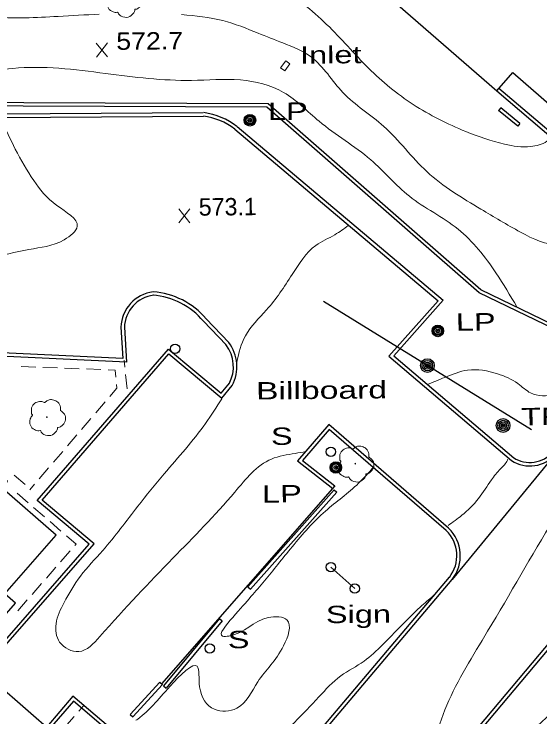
# Model space of a CAD drawing. Extents: x 2361708 to 2370558, y 6977955 to 6991887.
# Drawn here: x 2368753.8 to 2368899.2, y 6990434.2 to 6990628.6 of the extents above; entities that cross this region are included whole.
import ezdxf

# ---------------------------------------------------------------- set-up
doc = ezdxf.new("R2010")
doc.units = 0
doc.header["$LTSCALE"] = 1.9
for name, color, linetype, lineweight in [('11', 7, 'Continuous', 25), ('13', 7, 'Continuous', 13), ('2', 7, 'Continuous', 25), ('20', 7, 'Continuous', 25), ('21', 7, 'Continuous', 25), ('23', 7, 'Continuous', 25), ('29', 7, 'Continuous', 13), ('31', 7, 'Continuous', 13), ('35', 7, 'Continuous', 13), ('9', 7, 'Continuous', 13)]:
    doc.layers.add(name, color=color, linetype=linetype, lineweight=lineweight)

msp = doc.modelspace()

# ---------------------------------------------------------------- linework, layer by layer
at = {"layer": '11'}
for points in [[(2368803.061, 6990680.605), (2368887.263, 6990607.323), (2368891.675, 6990612.405), (2368910.239, 6990596.271), (2368917.905, 6990605.094), (2368925.478, 6990598.516), (2368956.5, 6990634.183), (2368949.038, 6990640.673), (2368978.25, 6990674.242), (2368958.133, 6990691.742), (2368936.419, 6990666.784), (2368928.906, 6990673.312), (2368921.191, 6990664.449), (2368845.954, 6990729.906)], [(2368706.996, 6990535.603), (2368638.297, 6990456.356), (2368654.119, 6990442.636), (2368653.159, 6990441.537), (2368680.829, 6990417.559), (2368681.571, 6990418.406), (2368686.875, 6990413.786), (2368665.874, 6990389.665), (2368677.46, 6990379.585), (2368712.974, 6990420.375), (2368713.831, 6990419.623), (2368727.186, 6990434.921), (2368751.368, 6990413.81), (2368764.99, 6990429.41), (2368740.919, 6990450.423), (2368754.205, 6990465.65), (2368751.28, 6990468.202), (2368765.486, 6990484.458), (2368750.47, 6990497.575), (2368751.984, 6990499.31), (2368724.121, 6990523.666), (2368722.627, 6990521.962)]]:
    msp.add_lwpolyline(points, close=True, dxfattribs=at)
at = {"layer": '13'}
for p, q in [((2368784.236, 6990532.859), (2368784.445, 6990530.871)), ((2368759.814, 6990530.926), (2368755.812, 6990531.078)), ((2368765.816, 6990530.703), (2368761.815, 6990530.855)), ((2368771.818, 6990530.48), (2368767.817, 6990530.632)), ((2368777.821, 6990530.257), (2368773.819, 6990530.41)), ((2368784.654, 6990528.882), (2368785.062, 6990524.906)), ((2368785.271, 6990522.918), (2368785.271, 6990522.898)), ((2368776.405, 6990518.264), (2368779.006, 6990521.298)), ((2368772.498, 6990513.706), (2368775.099, 6990516.741)), ((2368768.602, 6990509.149), (2368771.203, 6990512.184)), ((2368764.695, 6990504.591), (2368767.296, 6990507.626)), ((2368760.788, 6990500.034), (2368763.389, 6990503.069)), ((2368753.868, 6990501.048), (2368756.883, 6990498.427)), ((2368758.176, 6990496.989), (2368759.482, 6990498.511)), ((2368754.706, 6990496.016), (2368757.731, 6990493.404)), ((2368759.243, 6990492.099), (2368762.268, 6990489.488)), ((2368763.78, 6990488.182), (2368766.806, 6990485.571)), ((2368769.348, 6990480.095), (2368766.716, 6990477.079)), ((2368765.401, 6990475.576), (2368762.77, 6990472.562)), ((2368761.454, 6990471.059), (2368758.822, 6990468.044)), ((2368757.506, 6990466.541), (2368754.875, 6990463.536)), ((2368773.046, 6990437.278), (2368771.74, 6990435.765)), ((2368770.434, 6990434.253), (2368767.823, 6990431.228))]:
    msp.add_line(p, q, dxfattribs=at)
for points in [[(2368781.962, 6990528.097), (2368781.792, 6990530.116), (2368779.821, 6990530.186)], [(2368780.302, 6990522.821), (2368782.22, 6990525.059), (2368782.13, 6990526.108)], [(2368768.318, 6990484.265), (2368770.98, 6990481.96), (2368770.664, 6990481.597)]]:
    msp.add_lwpolyline(points, dxfattribs=at)
at = {"layer": '2'}
for p, q in [((2368888.388, 6990602.604), (2368887.785, 6990601.858)), ((2368893.699, 6990598.294), (2368888.388, 6990602.604)), ((2368893.096, 6990597.548), (2368887.785, 6990601.858)), ((2368893.699, 6990598.294), (2368893.096, 6990597.548)), ((2368813.182, 6990537.734), (2368806.909, 6990544.265)), ((2368812.488, 6990537.068), (2368806.215, 6990543.599)), ((2368903.549, 6990506.893), (2368874.918, 6990472.179)), ((2368842.52, 6990498.072), (2368794.599, 6990443.323)), ((2368842.371, 6990497.01), (2368818.475, 6990470.171)), ((2368843.087, 6990496.367), (2368819.191, 6990469.528)), ((2368842.371, 6990497.01), (2368843.087, 6990496.367)), ((2368818.475, 6990470.171), (2368819.191, 6990469.528)), ((2368810.668, 6990461.357), (2368795.125, 6990442.738)), ((2368811.404, 6990460.744), (2368795.86, 6990442.125)), ((2368810.668, 6990461.357), (2368811.404, 6990460.744)), ((2368794.125, 6990443.768), (2368785.949, 6990434.83)), ((2368794.831, 6990443.125), (2368786.656, 6990434.187)), ((2368794.125, 6990443.768), (2368794.831, 6990443.125)), ((2368795.125, 6990442.738), (2368795.86, 6990442.125)), ((2368785.949, 6990434.83), (2368786.656, 6990434.187))]:
    msp.add_line(p, q, dxfattribs=at)
for points in [[(2368887.886, 6990608.059), (2368913.746, 6990586.094), (2368909.564, 6990581.064)], [(2368887.263, 6990607.323), (2368912.397, 6990585.981), (2368903.222, 6990574.913)], [(2368913.951, 6990537.274), (2368882.916, 6990552.269), (2368824.074, 6990603.741), (2368711.364, 6990604.229), (2368623.522, 6990603.912)], [(2368913.529, 6990536.41), (2368882.384, 6990551.464), (2368823.713, 6990602.788), (2368711.363, 6990603.268), (2368623.522, 6990602.952)], [(2368623.568, 6990600.173), (2368707.447, 6990600.681), (2368806.156, 6990601.31)], [(2368623.577, 6990599.213), (2368707.456, 6990599.721), (2368806.165, 6990600.35)], [(2368814.87, 6990596.733), (2368871.064, 6990549.296), (2368857.45, 6990533.946), (2368891.356, 6990505.097)], [(2368815.493, 6990597.469), (2368872.433, 6990549.399), (2368858.819, 6990534.039), (2368891.979, 6990505.833)], [(2368996.914, 6990567.865), (2368920.861, 6990477.417), (2368836.413, 6990376.958), (2368777.799, 6990307.707)], [(2368997.649, 6990567.252), (2368921.597, 6990476.803), (2368837.149, 6990376.334), (2368778.535, 6990307.084)], [(2368783.38, 6990541.931), (2368783.902, 6990533.326), (2368709.045, 6990536.823), (2368624.356, 6990539.467), (2368627.356, 6990437.531), (2368654.02, 6990440.485)], [(2368784.339, 6990541.99), (2368784.922, 6990532.315), (2368709.004, 6990535.863), (2368625.345, 6990538.476), (2368628.286, 6990438.6), (2368653.91, 6990441.444)], [(2368744.289, 6990447.324), (2368774.57, 6990481.964), (2368760.265, 6990494.049), (2368796.498, 6990535.915), (2368811.125, 6990523.714), (2368813.409, 6990526.476)], [(2368745.025, 6990446.701), (2368775.94, 6990482.067), (2368761.624, 6990494.151), (2368796.61, 6990534.577), (2368811.248, 6990522.355), (2368814.145, 6990525.863)], [(2368873.953, 6990486.41), (2368840.879, 6990515.047), (2368832.164, 6990504.973), (2368841.928, 6990497.316)], [(2368873.32, 6990485.685), (2368840.972, 6990513.687), (2368833.553, 6990505.107), (2368842.52, 6990498.072)], [(2368717.185, 6990288.919), (2368794.17, 6990378.056), (2368874.182, 6990472.802)], [(2368717.911, 6990288.296), (2368794.897, 6990377.433), (2368874.918, 6990472.179)], [(2368782.391, 6990429.386), (2368770.131, 6990439.92), (2368762.861, 6990431.45)], [(2368781.768, 6990428.66), (2368770.234, 6990438.561), (2368763.607, 6990430.837)]]:
    msp.add_lwpolyline(points, dxfattribs=at)
for centre, radius, start, end in [((2368803.828, 6990582.444), 18.058, 52.30519, 82.564), ((2368803.828, 6990582.444), 19.018, 52.30519, 82.564), ((2368793.54, 6990541.657), 10.163, 96.90872, 178.45638), ((2368790.794, 6990530.805), 20.997, 39.87055, 85.84105), ((2368793.54, 6990541.657), 9.203, 96.90872, 178.45638), ((2368790.794, 6990530.805), 20.037, 39.87055, 85.84105), ((2368804.367, 6990531.044), 10.106, 332.08022, 37.19742), ((2368804.367, 6990531.044), 11.066, 332.08022, 37.19742), ((2368896.438, 6990512.877), 9.293, 236.84602, 319.91801), ((2368896.438, 6990512.877), 8.333, 236.84602, 319.91801), ((2318071.367, 7041248.644), 71901.899, 314.92877, 315.1113), ((2368866.59, 6990478.762), 9.656, 321.67388, 46.0885), ((2368866.59, 6990478.762), 10.616, 321.67388, 46.0885)]:
    msp.add_arc(centre, radius, start, end, dxfattribs=at)
at = {"layer": '20'}
for centre, radius in [((2368819.047, 6990599.203), 1.6), ((2368819.047, 6990599.203), 1.3), ((2368819.047, 6990599.203), 1), ((2368819.047, 6990599.203), 0.539), ((2368819.047, 6990599.203), 0.192), ((2368870.984, 6990540.935), 1.6), ((2368870.984, 6990540.935), 1.3), ((2368870.984, 6990540.935), 1), ((2368870.984, 6990540.935), 0.539), ((2368870.984, 6990540.935), 0.192), ((2368889.024, 6990514.775), 1.9), ((2368889.024, 6990514.775), 1.442), ((2368889.024, 6990514.775), 0.973), ((2368889.024, 6990514.775), 0.539), ((2368889.024, 6990514.775), 0.192), ((2368842.792, 6990503.155), 1.6), ((2368842.792, 6990503.155), 1.3), ((2368842.792, 6990503.155), 1), ((2368842.792, 6990503.155), 0.539), ((2368842.792, 6990503.155), 0.192)]:
    msp.add_circle(centre, radius, dxfattribs=at)
at = {"layer": '21'}
for p, q in [((2368896.845, 6990513.56), (2368839.385, 6990549.094)), ((2368848.031, 6990469.683), (2368841.435, 6990475.59))]:
    msp.add_line(p, q, dxfattribs=at)
for centre, radius in [((2368868.115, 6990531.327), 1.9), ((2368868.115, 6990531.327), 1.442), ((2368868.115, 6990531.327), 0.973), ((2368868.115, 6990531.327), 0.539), ((2368868.115, 6990531.327), 0.192), ((2368841.42, 6990507.522), 1.3), ((2368841.42, 6990475.59), 1.3), ((2368848.017, 6990469.682), 1.3), ((2368807.947, 6990453.111), 1.3)]:
    msp.add_circle(centre, radius, dxfattribs=at)
at = {"layer": '23'}
msp.add_circle((2368798.347, 6990536.013), 1.3, dxfattribs=at)
at = {"layer": '29'}
for centre in [(2368762.926, 6990517.075), (2368848.162, 6990504.216)]:
    msp.add_circle(centre, 0.1, dxfattribs=at)
for points in [[(2368788.018, 6990634.65), (2368789.158, 6990633.59), (2368789.443, 6990632.003), (2368788.735, 6990630.676), (2368788.081, 6990630.13), (2368787.413, 6990629.913), (2368787.263, 6990629.902), (2368787.244, 6990629.792), (2368786.922, 6990628.889), (2368785.383, 6990627.724), (2368783.491, 6990628.006), (2368782.591, 6990628.947), (2368782.521, 6990629.077), (2368782.401, 6990629.056), (2368781.19, 6990629.174), (2368779.92, 6990630.172), (2368779.574, 6990631.809), (2368779.944, 6990632.833), (2368780.27, 6990633.276), (2368780.34, 6990633.327)], [(2368758.96, 6990517.647), (2368758.98, 6990517.658), (2368758.899, 6990517.727), (2368758.663, 6990518.354), (2368758.701, 6990519.635), (2368759.589, 6990520.933), (2368760.894, 6990521.416), (2368762.016, 6990521.227), (2368762.247, 6990521.099), (2368762.317, 6990521.099), (2368762.367, 6990521.14), (2368762.714, 6990521.433), (2368763.58, 6990521.882), (2368764.791, 6990521.813), (2368765.906, 6990521.223), (2368766.64, 6990519.801), (2368766.648, 6990518.941)], [(2368766.638, 6990518.96), (2368767.778, 6990517.901), (2368768.063, 6990516.314), (2368767.356, 6990514.987), (2368766.701, 6990514.441), (2368766.033, 6990514.224), (2368765.883, 6990514.213), (2368765.864, 6990514.103), (2368765.543, 6990513.2), (2368764.004, 6990512.035), (2368762.111, 6990512.317), (2368761.212, 6990513.258), (2368761.14, 6990513.388), (2368761.021, 6990513.367), (2368759.81, 6990513.485), (2368758.54, 6990514.483), (2368758.195, 6990516.12), (2368758.565, 6990517.144), (2368758.891, 6990517.586), (2368758.96, 6990517.637)], [(2368844.197, 6990504.788), (2368844.217, 6990504.798), (2368844.136, 6990504.868), (2368843.9, 6990505.495), (2368843.937, 6990506.775), (2368844.825, 6990508.074), (2368846.131, 6990508.557), (2368847.252, 6990508.368), (2368847.484, 6990508.24), (2368847.554, 6990508.24), (2368847.603, 6990508.281), (2368847.951, 6990508.574), (2368848.817, 6990509.022), (2368850.027, 6990508.954), (2368851.143, 6990508.364), (2368851.876, 6990506.941), (2368851.885, 6990506.081)], [(2368851.874, 6990506.101), (2368853.015, 6990505.042), (2368853.3, 6990503.455), (2368852.592, 6990502.128), (2368851.937, 6990501.582), (2368851.269, 6990501.365), (2368851.12, 6990501.354), (2368851.101, 6990501.244), (2368850.779, 6990500.341), (2368849.24, 6990499.176), (2368847.347, 6990499.458), (2368846.448, 6990500.399), (2368846.377, 6990500.529), (2368846.257, 6990500.508), (2368845.046, 6990500.626), (2368843.777, 6990501.624), (2368843.431, 6990503.261), (2368843.801, 6990504.284), (2368844.127, 6990504.727), (2368844.197, 6990504.778)]]:
    msp.add_spline(points, degree=3, dxfattribs=at)
at = {"layer": '31'}
for p, q in [((2368779.668, 6990616.699), (2368776.551, 6990620.55)), ((2368776.589, 6990616.67), (2368779.631, 6990620.579)), ((2368802.466, 6990570.844), (2368799.349, 6990574.695)), ((2368799.386, 6990570.815), (2368802.429, 6990574.724))]:
    msp.add_line(p, q, dxfattribs=at)
at = {"layer": '35'}
for points in [[(2368833.891, 6990631.396), (2368840.245, 6990625.727), (2368851.851, 6990613.596), (2368864.177, 6990603.563), (2368878.689, 6990596.101), (2368889.433, 6990592.583), (2368896.65, 6990591.931), (2368901.156, 6990593.384), (2368902.962, 6990594.882)], [(2368892.832, 6990547.573), (2368887.062, 6990556.968), (2368876.566, 6990569.089), (2368863.129, 6990578.202), (2368852.422, 6990588.281), (2368838.17, 6990598.925), (2368828.364, 6990606.882), (2368816.391, 6990610.348), (2368802.891, 6990610.23), (2368779.121, 6990612.154), (2368753.467, 6990613.54), (2368734.81, 6990614.202), (2368730.806, 6990617.704), (2368733.042, 6990622.336), (2368739.282, 6990627.635), (2368747.371, 6990627.812), (2368766.021, 6990627.92), (2368777.405, 6990628.568)], [(2368800.158, 6990628.425), (2368811.574, 6990626.774), (2368821.308, 6990623.276), (2368828.124, 6990620.591), (2368836.032, 6990616.646), (2368844.735, 6990606.898), (2368856.024, 6990597.515), (2368867.944, 6990584.998), (2368882.904, 6990574.61), (2368893.845, 6990568.264), (2368904.588, 6990564.856), (2368909.347, 6990566.021)], [(2369047.828, 6990605.451), (2369038.394, 6990593.231), (2369027.418, 6990575.906), (2369015.841, 6990558.825), (2369000.65, 6990535.639), (2368993.146, 6990516.056), (2368986.096, 6990501.379), (2368978.606, 6990487.716), (2368969.405, 6990472.988), (2368958.108, 6990456.92), (2368955.454, 6990452.025), (2368953.073, 6990437.411), (2368952.752, 6990420.737), (2368959.614, 6990409.992), (2368963.269, 6990401.087), (2368969.023, 6990386.05), (2368979.207, 6990379.327), (2368988.134, 6990377.652), (2368992.144, 6990375.52), (2368991.785, 6990372.277), (2368987.467, 6990362.585), (2368986.816, 6990353.218), (2368988.815, 6990341.807), (2368989.62, 6990331.804), (2368986.922, 6990311.667), (2368979.307, 6990292.194), (2368965.455, 6990270.221), (2368943.017, 6990245.776), (2368913.099, 6990212.86), (2368880.694, 6990176.38), (2368844.682, 6990139.715), (2368811.712, 6990113.21), (2368778.447, 6990087.292), (2368739.578, 6990051.33), (2368711.829, 6990035.275), (2368686.864, 6990022.057), (2368673.109, 6990014.046), (2368669.745, 6990012.454), (2368668.706, 6990013.324), (2368669.63, 6990016.033), (2368674.153, 6990022.016), (2368684.646, 6990033.407), (2368697.173, 6990050.577), (2368697.763, 6990054.743), (2368695.615, 6990054.522), (2368688.933, 6990050.498), (2368671.541, 6990036.962), (2368648.494, 6990028.152), (2368625.507, 6990018.213), (2368603.069, 6990007.409), (2368581.573, 6989999.594), (2368572.511, 6989995.447), (2368567.234, 6989993.027)], [(2368750.303, 6990599.249), (2368754.189, 6990591.245), (2368759.272, 6990582.554), (2368765.689, 6990575.634), (2368771.303, 6990569.877), (2368767.698, 6990566.163), (2368757.964, 6990563.48), (2368746.716, 6990561.113), (2368725.647, 6990557.732), (2368715.905, 6990551.519), (2368706.461, 6990544.629), (2368702.523, 6990540.151), (2368700.997, 6990537.577)], [(2368967.606, 6990582.186), (2368963.011, 6990573.142), (2368950.064, 6990556.068), (2368934.8, 6990537.382), (2368918.347, 6990512.444), (2368903.121, 6990488.888), (2368884.755, 6990457.852), (2368873.469, 6990437.443), (2368869.841, 6990426.688), (2368869.607, 6990419.806), (2368870.812, 6990418.177)], [(2368815.403, 6990532.285), (2368817.784, 6990539.559), (2368823.606, 6990546.734), (2368830.714, 6990556.502), (2368837.277, 6990564.585), (2368842.529, 6990567.545), (2368846.225, 6990570.1)], [(2368867.995, 6990526.066), (2368872.936, 6990528.082), (2368879.227, 6990530.083), (2368887.487, 6990529.072), (2368893.114, 6990526.365), (2368896.638, 6990523.768), (2368903.583, 6990523.264), (2368910.815, 6990526.333), (2368911.986, 6990530.355), (2368912.765, 6990533.622), (2368913.749, 6990536.392)], [(2368983.929, 6990531.529), (2368979.435, 6990519.356), (2368975.701, 6990506), (2368972.153, 6990495.326), (2368965.023, 6990482.667), (2368952.28, 6990464.985), (2368944.692, 6990449.112), (2368936.279, 6990436.661), (2368930.708, 6990428.388), (2368926.974, 6990420.332), (2368923.178, 6990407.345), (2368925.818, 6990397.9), (2368929.492, 6990388.004), (2368932.253, 6990381.66), (2368935.154, 6990377.288), (2368935.872, 6990367.074), (2368936.658, 6990350.711), (2368934.899, 6990336.894), (2368925.545, 6990315.203), (2368919.061, 6990298.721), (2368917.665, 6990291.017), (2368922.007, 6990291.848), (2368928.932, 6990298.725), (2368940.303, 6990308.073), (2368954.807, 6990321.422), (2368956.934, 6990318.642), (2368952.658, 6990309.771), (2368947.879, 6990300.145), (2368939.818, 6990283.488), (2368927.075, 6990259.465), (2368910.767, 6990240.319), (2368886.835, 6990212.09), (2368866.726, 6990187.627), (2368845.138, 6990163.161), (2368822.496, 6990139.104), (2368799.648, 6990117.845), (2368778.178, 6990104.05), (2368756.592, 6990085.654), (2368734.588, 6990065.974), (2368713.09, 6990048.828), (2368704.692, 6990045.508), (2368705.15, 6990046.662), (2368709.481, 6990052.884), (2368718.059, 6990061.596), (2368727.733, 6990071.708), (2368736.854, 6990082.166), (2368748.659, 6990097.399), (2368759.795, 6990109.476), (2368764.382, 6990117.239), (2368763.943, 6990120.186), (2368757.319, 6990118.552), (2368746.862, 6990109.793), (2368726.432, 6990091.817), (2368699.934, 6990071.484), (2368679.435, 6990058.628), (2368654.88, 6990046.464), (2368626.237, 6990035.071), (2368603.78, 6990024.176), (2368586.487, 6990016.992), (2368573.437, 6990012.767), (2368565.504, 6990008.782), (2368560.239, 6990006.131), (2368556.575, 6990003.426)], [(2368811.229, 6990522.185), (2368806.774, 6990515.362), (2368795.336, 6990501.413), (2368788.042, 6990492.433), (2368778.347, 6990480.2), (2368772.174, 6990473.091), (2368767.654, 6990465.777), (2368765.46, 6990459.936), (2368766.428, 6990454.855), (2368771.723, 6990452.246), (2368777.534, 6990456.421), (2368797.749, 6990478.074), (2368814.875, 6990496.359), (2368824.979, 6990505.495), (2368831.584, 6990507.048), (2368834.47, 6990507.536)], [(2368873.816, 6990487.099), (2368877.61, 6990489.925), (2368882.235, 6990494.59), (2368885.827, 6990499.734), (2368888.288, 6990502.778), (2368890.235, 6990505.166), (2368890.313, 6990505.347)], [(2368853.291, 6990503.345), (2368849.094, 6990498.804), (2368839.887, 6990491.076), (2368830.71, 6990481.229), (2368823.089, 6990471.836), (2368814.315, 6990461.702), (2368811.494, 6990456.504), (2368813.214, 6990456.541), (2368824.116, 6990461.635), (2368829.313, 6990460.954), (2368828.341, 6990453.835), (2368821.215, 6990443.876), (2368815.415, 6990436.571), (2368809.217, 6990436.272), (2368805.138, 6990442.464), (2368804.463, 6990448.197), (2368796.985, 6990442.656), (2368788.012, 6990433.58), (2368787.525, 6990433.225)], [(2368789.929, 6990320.343), (2368790.53, 6990320.348), (2368797.873, 6990325.298), (2368807.423, 6990333.68), (2368817.733, 6990344.318), (2368829.52, 6990357.271), (2368840.79, 6990369.879), (2368857.89, 6990388.953), (2368868.503, 6990400.184), (2368882.774, 6990414.871), (2368900.904, 6990433.954), (2368914.357, 6990446.283), (2368927.592, 6990458.41), (2368938.738, 6990467.296), (2368945.543, 6990470.961), (2368944.236, 6990466.448), (2368939.885, 6990460.207), (2368933.405, 6990450.725), (2368923.326, 6990435.878), (2368917.886, 6990422.216), (2368911.041, 6990411.13), (2368905.079, 6990401.823), (2368900.974, 6990394.023), (2368900.322, 6990384.766), (2368901.314, 6990374.025), (2368904.437, 6990367.355), (2368904.31, 6990359.763), (2368903.563, 6990354.106), (2368901.129, 6990347.222), (2368896.475, 6990339.217), (2368894.175, 6990318.195), (2368888.579, 6990298.791), (2368874.725, 6990269.767), (2368859.183, 6990244.758), (2368839.662, 6990217.401), (2368811.187, 6990186.269), (2368782.802, 6990157.217), (2368754.567, 6990130.256), (2368727.088, 6990107.924), (2368698.455, 6990089.211), (2368672.208, 6990074.11), (2368648.698, 6990060.265), (2368628.721, 6990050.445), (2368613.068, 6990044.306), (2368603.074, 6990040.52), (2368593.252, 6990034.387), (2368582.867, 6990026.477), (2368572.981, 6990018.563), (2368564.602, 6990014.263), (2368560.596, 6990012.755), (2368556.513, 6990009.896), (2368554.167, 6990007.363), (2368553.067, 6990006.373)], [(2368668.236, 6990322.184), (2368674.54, 6990317.624), (2368682.079, 6990311.465), (2368688.665, 6990311.909), (2368693.65, 6990317.666), (2368704.856, 6990325.583), (2368716.448, 6990336.934), (2368724.09, 6990345.187), (2368734.348, 6990355.925), (2368738.516, 6990355.075), (2368741.207, 6990353.96), (2368744.07, 6990356.878), (2368747.47, 6990361.1), (2368753.712, 6990362.98), (2368758.694, 6990361.737), (2368763.812, 6990365.176), (2368767.51, 6990370.542), (2368769.182, 6990376.708), (2368768.22, 6990383.179), (2368765.899, 6990389.667), (2368768.378, 6990394.931), (2368773.708, 6990395.012), (2368781.362, 6990392.515), (2368786.172, 6990392.511), (2368792.969, 6990397.095), (2368801.23, 6990406.514), (2368807.472, 6990414.794), (2368815.842, 6990422.124), (2368824.626, 6990426.918), (2368831.332, 6990432.662), (2368838.086, 6990439.696), (2368844.131, 6990445.494), (2368850.602, 6990449.617), (2368855.66, 6990454.085), (2368862.375, 6990460.899), (2368866.547, 6990464.959), (2368870.217, 6990468.094)], [(2368672.622, 6990193.42), (2368677.499, 6990196.877), (2368689.448, 6990206.571), (2368704.224, 6990219.602), (2368717.195, 6990232.226), (2368732.475, 6990247.012), (2368743.676, 6990258.509), (2368759.297, 6990275.259), (2368769.621, 6990286.508), (2368783.909, 6990302.554), (2368801.545, 6990320.823), (2368816.251, 6990336.034), (2368827.604, 6990348.413), (2368841.891, 6990363.499), (2368853.954, 6990376.915), (2368873.879, 6990397.545), (2368883.733, 6990407.64), (2368895.263, 6990419.25), (2368903.392, 6990427.818), (2368912.434, 6990437.134)]]:
    msp.add_spline(points, degree=3, dxfattribs=at)
at = {"layer": '9'}
msp.add_lwpolyline([(2368828.657, 6990612.885), (2368830.079, 6990614.799), (2368828.951, 6990615.638), (2368827.529, 6990613.725)], close=True, dxfattribs=at)

# ---------------------------------------------------------------- texts
at = {"layer": '20'}
for s, width, p in [('  LP', 1.4, (2368819.046, 6990599.203)), ('  LP', 1.4, (2368870.984, 6990540.935)), ('Billboard', 1.45, (2368820.752, 6990521.956)), ('  TFP', 1.4, (2368889.024, 6990514.775)), ('  LP', 1.4, (2368817.424, 6990493.383)), ('Sign', 1.4, (2368840.062, 6990460.087))]:
    msp.add_text(s, height=4.8, rotation=0.545, dxfattribs=dict(at, width=width)).set_placement(p)
at = {"layer": '21', "width": 1.4}
for p in [(2368819.882, 6990509.337), (2368807.937, 6990453.1)]:
    msp.add_text('  S', height=4.8, rotation=0.545, dxfattribs=at).set_placement(p)
at = {"layer": '31', "width": 1.15}
msp.add_text('572.7', height=4.8, rotation=0.545, dxfattribs=at).set_placement((2368782.109, 6990618.663))
at = {"layer": '31'}
msp.add_text('573.1', height=4.8, rotation=0.545, dxfattribs=at).set_placement((2368804.907, 6990572.807))
at = {"layer": '9', "width": 1.4}
msp.add_text('Inlet', height=4.8, rotation=0.545, dxfattribs=at).set_placement((2368832.918, 6990614.826))

doc.saveas('drawing.dxf')
